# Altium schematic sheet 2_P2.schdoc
size 307 x 218 mm; Symbol: Drawing-Symbol_A4; Device: Drawing-Symbol_A4; @Project Name: 5x6V2_Left; @Page Count: 2; @Update Date: 2025-07-05; @Create Date: 2025-07-02; @Schematic Name: 5x6V2; @Page No: 2; @Page Name: P2; Company: EasyEDA.com; Version: V1.0; Page Size: A4; @Create Time: 00:03:01; @Update Time: 13:08:09; Width: 1170; Height: 825; Region Start: 1; X Region Count: 6; Y Region Count: 4; Blade Width: 10; Title Block Position: 3; @Board Name: 5x6V2
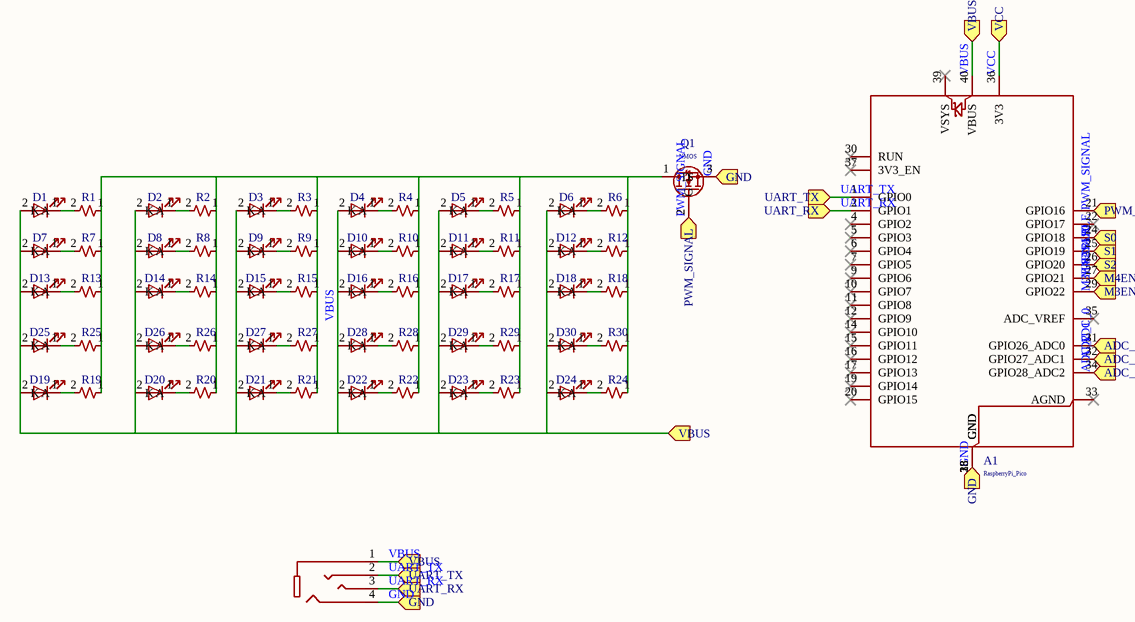
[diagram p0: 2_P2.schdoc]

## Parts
A1  value RaspberryPi_Pico  [Module:RaspberryPi_Pico_Common_Unspecified]  (hidden comment: MCU_Module_RaspberryPi_Pico)
CN1  HC-PJ-320AB  [AUDIO-SMD_HC-PJ-320A]  (value not drawn)
D1  XL-3216UWC-FB  [LED-SMD_L3.2-W1.6-RD-EH_WHITE]  (value not drawn)
D2  XL-3216UWC-FB  [LED-SMD_L3.2-W1.6-RD-EH_WHITE]  (value not drawn)
D3  XL-3216UWC-FB  [LED-SMD_L3.2-W1.6-RD-EH_WHITE]  (value not drawn)
D4  XL-3216UWC-FB  [LED-SMD_L3.2-W1.6-RD-EH_WHITE]  (value not drawn)
D5  XL-3216UWC-FB  [LED-SMD_L3.2-W1.6-RD-EH_WHITE]  (value not drawn)
D6  XL-3216UWC-FB  [LED-SMD_L3.2-W1.6-RD-EH_WHITE]  (value not drawn)
D7  XL-3216UWC-FB  [LED-SMD_L3.2-W1.6-RD-EH_WHITE]  (value not drawn)
D8  XL-3216UWC-FB  [LED-SMD_L3.2-W1.6-RD-EH_WHITE]  (value not drawn)
D9  XL-3216UWC-FB  [LED-SMD_L3.2-W1.6-RD-EH_WHITE]  (value not drawn)
D10  XL-3216UWC-FB  [LED-SMD_L3.2-W1.6-RD-EH_WHITE]  (value not drawn)
D11  XL-3216UWC-FB  [LED-SMD_L3.2-W1.6-RD-EH_WHITE]  (value not drawn)
D12  XL-3216UWC-FB  [LED-SMD_L3.2-W1.6-RD-EH_WHITE]  (value not drawn)
D13  XL-3216UWC-FB  [LED-SMD_L3.2-W1.6-RD-EH_WHITE]  (value not drawn)
D14  XL-3216UWC-FB  [LED-SMD_L3.2-W1.6-RD-EH_WHITE]  (value not drawn)
D15  XL-3216UWC-FB  [LED-SMD_L3.2-W1.6-RD-EH_WHITE]  (value not drawn)
D16  XL-3216UWC-FB  [LED-SMD_L3.2-W1.6-RD-EH_WHITE]  (value not drawn)
D17  XL-3216UWC-FB  [LED-SMD_L3.2-W1.6-RD-EH_WHITE]  (value not drawn)
D18  XL-3216UWC-FB  [LED-SMD_L3.2-W1.6-RD-EH_WHITE]  (value not drawn)
D19  XL-3216UWC-FB  [LED-SMD_L3.2-W1.6-RD-EH_WHITE]  (value not drawn)
D20  XL-3216UWC-FB  [LED-SMD_L3.2-W1.6-RD-EH_WHITE]  (value not drawn)
D21  XL-3216UWC-FB  [LED-SMD_L3.2-W1.6-RD-EH_WHITE]  (value not drawn)
D22  XL-3216UWC-FB  [LED-SMD_L3.2-W1.6-RD-EH_WHITE]  (value not drawn)
D23  XL-3216UWC-FB  [LED-SMD_L3.2-W1.6-RD-EH_WHITE]  (value not drawn)
D24  XL-3216UWC-FB  [LED-SMD_L3.2-W1.6-RD-EH_WHITE]  (value not drawn)
D25  XL-3216UWC-FB  [LED-SMD_L3.2-W1.6-RD-EH_WHITE]  (value not drawn)
D26  XL-3216UWC-FB  [LED-SMD_L3.2-W1.6-RD-EH_WHITE]  (value not drawn)
D27  XL-3216UWC-FB  [LED-SMD_L3.2-W1.6-RD-EH_WHITE]  (value not drawn)
D28  XL-3216UWC-FB  [LED-SMD_L3.2-W1.6-RD-EH_WHITE]  (value not drawn)
D29  XL-3216UWC-FB  [LED-SMD_L3.2-W1.6-RD-EH_WHITE]  (value not drawn)
D30  XL-3216UWC-FB  [LED-SMD_L3.2-W1.6-RD-EH_WHITE]  (value not drawn)
Q1  value NMOS  [Package_TO_SOT_SMD:SOT-23-3]  (hidden comment: Simulation_SPICE_NMOS)
R1  Device_R_Small_US  [R1206]  (value not drawn)
R2  Device_R_Small_US  [R1206]  (value not drawn)
R3  Device_R_Small_US  [R1206]  (value not drawn)
R4  Device_R_Small_US  [R1206]  (value not drawn)
R5  Device_R_Small_US  [R1206]  (value not drawn)
R6  Device_R_Small_US  [R1206]  (value not drawn)
R7  Device_R_Small_US  [R1206]  (value not drawn)
R8  Device_R_Small_US  [R1206]  (value not drawn)
R9  Device_R_Small_US  [R1206]  (value not drawn)
R10  Device_R_Small_US  [R1206]  (value not drawn)
R11  Device_R_Small_US  [R1206]  (value not drawn)
R12  Device_R_Small_US  [R1206]  (value not drawn)
R13  Device_R_Small_US  [R1206]  (value not drawn)
R14  Device_R_Small_US  [R1206]  (value not drawn)
R15  Device_R_Small_US  [R1206]  (value not drawn)
R16  Device_R_Small_US  [R1206]  (value not drawn)
R17  Device_R_Small_US  [R1206]  (value not drawn)
R18  Device_R_Small_US  [R1206]  (value not drawn)
R19  Device_R_Small_US  [R1206]  (value not drawn)
R20  Device_R_Small_US  [R1206]  (value not drawn)
R21  Device_R_Small_US  [R1206]  (value not drawn)
R22  Device_R_Small_US  [R1206]  (value not drawn)
R23  Device_R_Small_US  [R1206]  (value not drawn)
R24  Device_R_Small_US  [R1206]  (value not drawn)
R25  Device_R_Small_US  [R1206]  (value not drawn)
R26  Device_R_Small_US  [R1206]  (value not drawn)
R27  Device_R_Small_US  [R1206]  (value not drawn)
R28  Device_R_Small_US  [R1206]  (value not drawn)
R29  Device_R_Small_US  [R1206]  (value not drawn)
R30  Device_R_Small_US  [R1206]  (value not drawn)

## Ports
ADC_0 (in), ADC_1 (in), ADC_2 (in), GND (in), M3ENABLE (in), M4ENABLE (in), PWM_SIGNAL (in), S0 (in), S1 (in), S2 (in), UART_RX (in), UART_TX (in), VBUS (in), VCC (in)

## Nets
ADC_0: A1.31(GPIO26_ADC0) ; port ADC_0
ADC_1: A1.32(GPIO27_ADC1) ; port ADC_1
ADC_2: A1.34(GPIO28_ADC2) ; port ADC_2
GND: A1.3(GND) A1.8(GND) A1.13(GND) A1.18(GND) A1.23(GND) A1.28(GND) A1.38(GND) CN1.4 Q1.3(S) ; port GND
M3ENABLE: A1.29(GPIO22) ; port M3ENABLE
M4ENABLE: A1.27(GPIO21) ; port M4ENABLE
PWM_SIGNAL: A1.21(GPIO16) Q1.2(G) ; port PWM_SIGNAL
S0: A1.24(GPIO18) ; port S0
S1: A1.25(GPIO19) ; port S1
S2: A1.26(GPIO20) ; port S2
UART_RX: A1.2(GPIO1) CN1.3 ; port UART_RX
UART_TX: A1.1(GPIO0) CN1.2 ; port UART_TX
VBUS: A1.40(VBUS) CN1.1 D1.2(A) D2.2(A) D3.2(A) D4.2(A) D5.2(A) D6.2(A) D7.2(A) D8.2(A) D9.2(A) D10.2(A) D11.2(A) D12.2(A) D13.2(A) D14.2(A) D15.2(A) D16.2(A) D17.2(A) D18.2(A) D19.2(A) D20.2(A) D21.2(A) D22.2(A) D23.2(A) D24.2(A) D25.2(A) D26.2(A) D27.2(A) D28.2(A) D29.2(A) D30.2(A) ; port VBUS
VCC: A1.36(3V3) ; port VCC
NetD1_1: D1.1(K) R1.2
NetD2_1: D2.1(K) R2.2
NetD3_1: D3.1(K) R3.2
NetD4_1: D4.1(K) R4.2
NetD5_1: D5.1(K) R5.2
NetD6_1: D6.1(K) R6.2
NetD7_1: D7.1(K) R7.2
NetD8_1: D8.1(K) R8.2
NetD9_1: D9.1(K) R9.2
NetD10_1: D10.1(K) R10.2
NetD11_1: D11.1(K) R11.2
NetD12_1: D12.1(K) R12.2
NetD13_1: D13.1(K) R13.2
NetD14_1: D14.1(K) R14.2
NetD15_1: D15.1(K) R15.2
NetD16_1: D16.1(K) R16.2
NetD17_1: D17.1(K) R17.2
NetD18_1: D18.1(K) R18.2
NetD19_1: D19.1(K) R19.2
NetD20_1: D20.1(K) R20.2
NetD21_1: D21.1(K) R21.2
NetD22_1: D22.1(K) R22.2
NetD23_1: D23.1(K) R23.2
NetD24_1: D24.1(K) R24.2
NetD25_1: D25.1(K) R25.2
NetD26_1: D26.1(K) R26.2
NetD27_1: D27.1(K) R27.2
NetD28_1: D28.1(K) R28.2
NetD29_1: D29.1(K) R29.2
NetD30_1: D30.1(K) R30.2
NetQ1_1: Q1.1(D) R1.1 R2.1 R3.1 R4.1 R5.1 R6.1 R7.1 R8.1 R9.1 R10.1 R11.1 R12.1 R13.1 R14.1 R15.1 R16.1 R17.1 R18.1 R19.1 R20.1 R21.1 R22.1 R23.1 R24.1 R25.1 R26.1 R27.1 R28.1 R29.1 R30.1

Not connected (* = marked no-connect by the designer): A1 4(GPIO2)* 5(GPIO3)* 6(GPIO4)* 7(GPIO5)* 9(GPIO6)* 10(GPIO7)* 11(GPIO8)* 12(GPIO9)* 14(GPIO10)* 15(GPIO11)* 16(GPIO12)* 17(GPIO13)* 19(GPIO14)* 20(GPIO15)* 22(GPIO17)* 30(RUN)* 33(AGND)* 35(ADC_VREF)* 37(3V3_EN)* 39(VSYS)*

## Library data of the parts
A1 = MCU_Module_RaspberryPi_Pico: ki_fp_filters: RaspberryPi?Pico?Common* RaspberryPi?Pico?SMD*; Add into BOM: yes
CN1 = HC-PJ-320AB: Manufacturer: HC(虹成电子); Add into BOM: yes; Connector Type: 3.5mm Headphone Jack; Current Rating: 500mA; Voltage Rating (Max): 30V
D1-D30 = XL-3216UWC-FB: Manufacturer: XINGLIGHT(成兴光); Symbol: Device_LED; Add into BOM: yes; Emitted Color: White; Forward Voltage (VF): 2.6V~3V; Power Dissipation: 75mW; Forward Current: 2mA; Lens Color: 黄色透镜; Color Temperature: 12000K~27000K; Viewing Angle: 120°; Mounting Sytle: 反贴
Q1 = Simulation_SPICE_NMOS: Users: REF**; sim_type: VDMOS; sim_pins: 1=D 2=G 3=S; Add into BOM: yes
R1-R30 = Device_R_Small_US: ki_fp_filters: R_*; Add into BOM: yes; Origin Footprint: Resistor_SMD:R_1206_3216Metric_Pad1.30x1.75mm_HandSolder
